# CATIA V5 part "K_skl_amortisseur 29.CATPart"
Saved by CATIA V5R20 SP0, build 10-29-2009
Part number: skl_amortisseur 29
Publications: "longueur amortisseur", "longueur axe pivot", "liaison 28/29 sur 29", "droite appui verin droite", "Droite.1", "Droite.3", "Plan.-55"
Bounding box of the stored display mesh (mm): x -55 to 95, y 285 to 663.947, z 128.478 to 285
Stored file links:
  G:\Khaled_CFAO_2011\SIL\SIL_GR2\mdardier\Khaled\CAD_ThinkMOTION\K_skl_amortisseur 29.CATPart
  G:\Khaled_CFAO_2011\SIL\SIL_GR2\mdardier\Khaled\CAD_ThinkMOTION\K_skl_ass_tandem.CATProduct
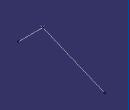
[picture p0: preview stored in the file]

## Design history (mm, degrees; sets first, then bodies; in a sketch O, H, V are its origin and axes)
External parameters (linked from other documents)
  `External.longueur amortisseur` = 410 mm
  `External.longueur axe pivot` = 150 mm
Set1
  Point1 "liaison 28/29 sur 29": linked copy from another document
  Line1 "droite appui verin droite": linked copy from another document
  Plane1 "Plan.-55": linked copy from another document
Set2
  Line2: type PtDir, RefPoint Point1, Direction Line1, Start 0, End 410 {= `External.longueur amortisseur`}
  Line3: type Normal, RefPoint Point1, RefSkin Plane1, Start 0, End 150 {= `External.longueur axe pivot`}
Body1 (main body)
